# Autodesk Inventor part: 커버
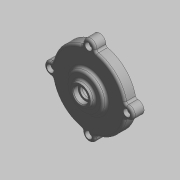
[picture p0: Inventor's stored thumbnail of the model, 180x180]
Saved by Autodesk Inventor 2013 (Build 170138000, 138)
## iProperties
Created: 2015-11
Part Number: 커버
Document SubType Name: 모델링
Designer: mdu
Material: 알루미늄 6061
Density: 2.71 g/cm^3
Mass: 196.659 g
Surface Area: 278.607 cm^2
Volume: 72.5678 cm^3
변환 표준: STEP AP214IS
파일 이름: C:\Users\SeoGD\Desktop\?쒗뿕\而ㅻ쾭-1.stp
전처리기: Build: 253, Release: 2010 SP1 - Date: Wed 07/29/2009
전송 단위: 밀리미터
불확실성: 0.01
Author: mdu
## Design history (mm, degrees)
sketch "스케치1"
  geometry: L1 (0, 0)-(0, 26); L2 (50, 0)-(50, 15); L3 (50, 15)-(25, 15); L4 (25, 15)-(25, 21); L5 (25, 21)-(15, 21); L6 (15, 21)-(13.66, 26); L7 (13.66, 26)-(10, 26); L8 (50, 0)-(45, 0); L9 (45, 0)-(45, 10); L10 (45, 10)-(14.5, 10); L11 (14.5, 10)-(13.266, 3); L12 (13.266, 3)-(11, 3); L13 (11, 3)-(11, 16); L14 (11, 16)-(7.5, 16); L15 (7.5, 16)-(7.5, 19); L16 (7.5, 19)-(10, 19); L17 (10, 19)-(10, 26)
  constraints: 34 end point, 10 parallel, 2 perpendicular, 2 point on line, 1 vertical
  dimensions: "d11" = 100 diameter of L2 L1; "d12" = 22 diameter of L13 L1; "d13" = 90 diameter of L9 L1; "d14" = 15 distance between parallel lines of L3 L8; "d15" = 10 distance between parallel lines of L8 L10; "d16" = 29 diameter of L10.end L1; "d17" = 100 deg angle of L11 L10; "d18" = 7 distance between parallel lines of L12 L10; "d19" = 13 distance between parallel lines of L14 L12; "d20" = 3 distance between parallel lines of L16 L14; "d21" = 15 diameter of L15 L1; "d22" = 20 diameter of L17 L1; "d23" = 30 diameter of L5.end L1; "d24" = 6 distance between parallel lines of L5 L3; "d25" = 50 diameter of L4 L1; "d26" = 105 deg angle of L5 L6; "d50" = 26 distance of L1.start L1.end
revolve "회전1" sketch "스케치1" stored, may be unused: angle "d27" = 90 deg
sketch "스케치2" dims "d29" = 104
  geometry: A1 r 8.5 centre (0, 52) between (8.074, 49.344) and (-8.074, 49.344); A2 r 50 centre (0, 0) between (-8.074, 49.344) and (8.074, 49.344) reference; 2 further points
  constraints: 4 point on circle, 2 vertical alignment, 1 centre point, 1 coincident, 2 other
  dimensions: "d28" = 17 diameter of A1
extrude "돌출1" join sketch "스케치2" stored distance "d30" = 10; taper "d31" = 0 deg
fillet "모깎기3" dims "d32" = 3
fillet "모깎기4" dims "d45" = 3, "d46" = 0.2
chamfer "모따기1" distance "d47" = 1; stored, may be unused: second distance "d48" = 2, angle "d49" = 45 deg
hole "구멍2" diameter "d38" = 5.5; stored, may be unused: countersink angle "d42" = 90 deg, drill point angle "d44" = 118 deg; dims "d39" = 6, "d40" = 9.5, "d41" = 5.4, "d43" = 8, "d54" = 10, "d55" = 10
node "솔리드1"
node "솔리드 본체"
node "곡면 본체"
pattern_circular "원형 패턴1" dims angle "d34" = 360 deg
pattern_circular "원형 패턴2" dims angle "d52" = 360 deg
node "솔리드2"
